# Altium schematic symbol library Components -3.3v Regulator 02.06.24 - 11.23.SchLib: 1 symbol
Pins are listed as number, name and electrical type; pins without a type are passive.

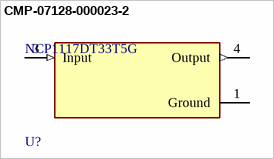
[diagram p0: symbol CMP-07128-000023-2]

## CMP-07128-000023-2
designator U?, comment NCP1117DT33T5G
IC REG LINEAR 3.3V 1A DPAK; Polarity: Positive; Input Bias Current: 6mA; Quiescent Current: 10mA; Output Type: Fixed; Number of Outputs: 1; Output Voltage Accuracy: 1%; Max Input Voltage: 20V; Dropout Voltage: 1.07V; Reference Voltage: 1.27V
footprint FP-369C-MFG
pins: 1 Ground (power), 3 Input (in), 4 Output (out)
